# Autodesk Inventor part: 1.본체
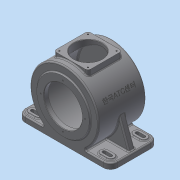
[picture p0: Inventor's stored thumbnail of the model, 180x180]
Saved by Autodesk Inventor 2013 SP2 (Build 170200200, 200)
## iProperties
Created: 2015-06
Part Number: 1.본체
Material: 일반
Document SubType Name: Modeling
Designer: dgall
Density: 1 g/cm^3
Author: dgall
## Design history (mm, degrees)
sketch "스케치1"
  geometry: L1 (-115, 59)-(115, 59); L2 (115, 59)-(115, -59); L3 (115, -59)-(-115, -59); L4 (-115, -59)-(-115, 59); 3 further points
  constraints: 8 end point, 2 midpoint, 2 parallel, 1 horizontal, 1 horizontal alignment, 1 perpendicular, 1 vertical alignment
  dimensions: "d0" = 230 distance of L1.start L1.end; "d2" = 118 distance of L3.end L1.start
extrude "돌출1" new body sketch "스케치1" distance "d3" = 14; taper "d4" = 0 deg
sketch "스케치2"
  geometry: L1 (71, 72)-(71, -62); L2 (71, 72)-(136, 72); L3 (136, 72)-(136, 59); L4 (136, 59)-(156, 59); L5 (156, 59)-(156, -59); L6 (156, -59)-(136, -59); L7 (136, -59)-(136, -62); L8 (136, -62)-(71, -62); L9 (-14, 59)-(-14, -59) reference; L10 (71, 64.5)-(86, 64.5); L11 (86, 64.5)-(86, 61.5); L12 (86, 61.5)-(94.5, 61.5); L13 (94.5, 61.5)-(94.5, 47.5); L14 (148, 51)-(148, -51); L15 (148, -51)-(118.5, -51); L16 (118.5, -51)-(118.5, -62); L17 (94.5, 47.5)-(100.368, 47.5); L18 (100.368, 47.5)-(102, 51); L19 (102, 51)-(148, 51); L20 (0, -59)-(0, 59) reference; 4 further points
  constraints: 36 end point, 9 parallel, 6 perpendicular, 3 midpoint, 2 point on line, 1 collinear, 1 horizontal alignment, 1 vertical
  dimensions: "d5" = 134 distance of L1.start L1.end; "d7" = 85 distance between parallel lines of L1 L9; "d8" = 118 distance of L4.end L5.end; "d9" = 13 distance of L2.end L3.end; "d10" = 170 diameter of L5 L1; "d11" = 130 diameter of L3 L1; "d12" = 130 diameter of L7 L1; "d13" = 30 diameter of L11 L1; "d14" = 47 diameter of L13 L1; "d15" = 154 diameter of L14 L1; "d16" = 95 diameter of L16 L1; "d17" = 11 distance of L15.end L16.end; "d18" = 3 distance of L10.end L11.end; "d19" = 14 distance of L12.end L13.end; "d23" = 115 deg angle of L19 L18; "d24" = 62 diameter of L18.end L1; "d25" = 3.5 distance between parallel lines of L17 L19; "d26" = 8 distance between parallel lines of L4 L19
revolve "회전1" stored, may be unused: angle "d27" = 90 deg
sketch "스케치3"
  geometry: L1 (74, 42.5)-(159, 42.5); L2 (159, 42.5)-(159, -42.5); L3 (159, -42.5)-(74, -42.5); L4 (74, -42.5)-(74, 42.5); L5 (-14, 59)-(-14, -59) reference; 2 further points
  constraints: 8 end point, 2 parallel, 2 perpendicular, 1 horizontal, 1 horizontal alignment, 1 midpoint
  dimensions: "d28" = 173 distance between parallel lines of L2 L5; "d29" = 85 distance of L1.start L1.end
extrude "돌출2" join sketch "스케치3" stored distance "d30" = 85; taper "d31" = 0 deg
sketch "스케치4"
  geometry: C1 r 35 at (42.5, 42.5); 1 further point
  constraints: 1 centre point, 1 coincident
  dimensions: "d32" = 70 diameter of C1
extrude "돌출3" cut sketch "스케치4" distance "d34" = 50; taper "d35" = 0 deg
revolve "회전2" stored, may be unused: angle "d36" = 90 deg
fillet "모깎기1" dims "d37" = 18
sketch "스케치5"
  geometry: L1 (-115, 59)-(-115, -59) reference; L2 (81, -32)-(97, -32); L3 (81, -50)-(97, -50); L4 (97, -37)-(81, -37); L5 (81, -45)-(97, -45); A1 r 9 centre (81, -41) between (81, -32) and (81, -50); A2 r 9 centre (97, -41) between (97, -50) and (97, -32); A3 r 18 centre (97, -41) between (97, -59) and (115, -41) reference; A4 r 4 centre (81, -41) between (81, -37) and (81, -45); A5 r 4 centre (97, -41) between (97, -45) and (97, -37); 1 further point
  constraints: 8 end point, 8 point on circle, 4 centre point, 3 tangent, 1 concentric, 1 equal radius, 1 horizontal alignment, 1 perpendicular, 3 other
  dimensions: "d38" = 16 distance of A2.centre A1.centre; "d40" = 18 diameter of A2; "d41" = 24 dimension on A5 A4
extrude "돌출4" join sketch "스케치5" distance "d42" = 17; taper "d43" = 0 deg
extrude "돌출5" cut sketch "스케치5" stored distance "d44" = 17; taper "d45" = 0 deg
sketch "스케치6"
  geometry: L1 (46.733, 0)-(97, 0) reference; L2 (97, 0)-(115, 0) reference; L3 (84.87, 66.297)-(109, 0); L4 (115, 0)-(115, -14) reference; A1 r 85 centre (0, 71) between (46.733, 0) and (-46.733, 0) reference; 1 further point
  constraints: 2 end point, 1 point on circle, 1 point on line
  dimensions: "d52" = 6 distance from line of L3.end L4; "d53" = 110 deg angle of L3 L2
feature "리브1" sketch "스케치6" dims "d54" = 1, "d55" = 15, "d56" = 0, "d57" = 0, "d58" = 1, "d59" = 1
fillet "모깎기2" dims "d62" = 7
hole "구멍1" diameter "d65" = 3.242; stored, may be unused: countersink angle "d69" = 90 deg, drill point angle "d71" = 118 deg; dims "d63" = 10, "d64" = 10, "d66" = 10, "d67" = 4, "d68" = 2, "d70" = 13
sketch "스케치8"
  geometry: C1 r 47.5 at (0, 0) reference; 2 further points
  constraints: 1 horizontal alignment
  dimensions: "d78" = 55 distance of C1.centre point (-55, 0)
hole "구멍2" sketch "스케치8" at (-55, 0) diameter "d79" = 3.242; stored, may be unused: countersink angle "d83" = 90 deg, drill point angle "d85" = 118 deg; dims "d80" = 10, "d81" = 4, "d82" = 2, "d84" = 13
fillet "모깎기3" dims "d89" = 0.3
fillet "모깎기4" dims "d90" = 3
chamfer "모따기1" distance "d91" = 1; stored, may be unused: second distance "d92" = 2, angle "d93" = 45 deg
fillet "모깎기5" dims "d94" = 3
fillet "모깎기6" dims "d95" = 3
fillet "모깎기7" dims "d96" = 3
fillet "모깎기8" dims "d97" = 3
node "작업축2"
sketch "스케치9"
  geometry: L1 (-77.036, 106.923)-(0, 71); L2 (-97, -14)-(97, -14) reference; A1 r 85 centre (0, 71) between (53.953, 5.318) and (-53.953, 5.318) reference; 2 further points
  constraints: 2 end point, 1 coincident, 1 point on circle, 1 vertical alignment
  dimensions: "d98" = 25 deg angle of L1 L2; "d99" = 85 distance from line of L2 L1.end
node "작업 평면4"
sketch "스케치10"
  geometry: 3 further points
  constraints: 1 coincident, 1 other
feature "엠보싱1" sketch "스케치10" dims "d0" = 230, "d2" = 118, "d5" = 134, "d7" = 85, "d8" = 118, "d9" = 13, "d10" = 170, "d11" = 130, "d12" = 130, "d13" = 30, "d14" = 47, "d15" = 154, "d16" = 95, "d17" = 11, "d18" = 3, "d19" = 14, "d23" = 115 deg, "d24" = 62, "d25" = 3.5, "d26" = 8, "d100" = 0.5, "d101" = 0
node "솔리드1"
pattern_linear "직사각형 패턴1" dims "d48" = 82, "d51" = 178
mirror "대칭1"
pattern_linear "직사각형 패턴2" dims "d74" = 71, "d77" = 71
pattern_circular "원형 패턴1" dims angle "d87" = 360 deg
